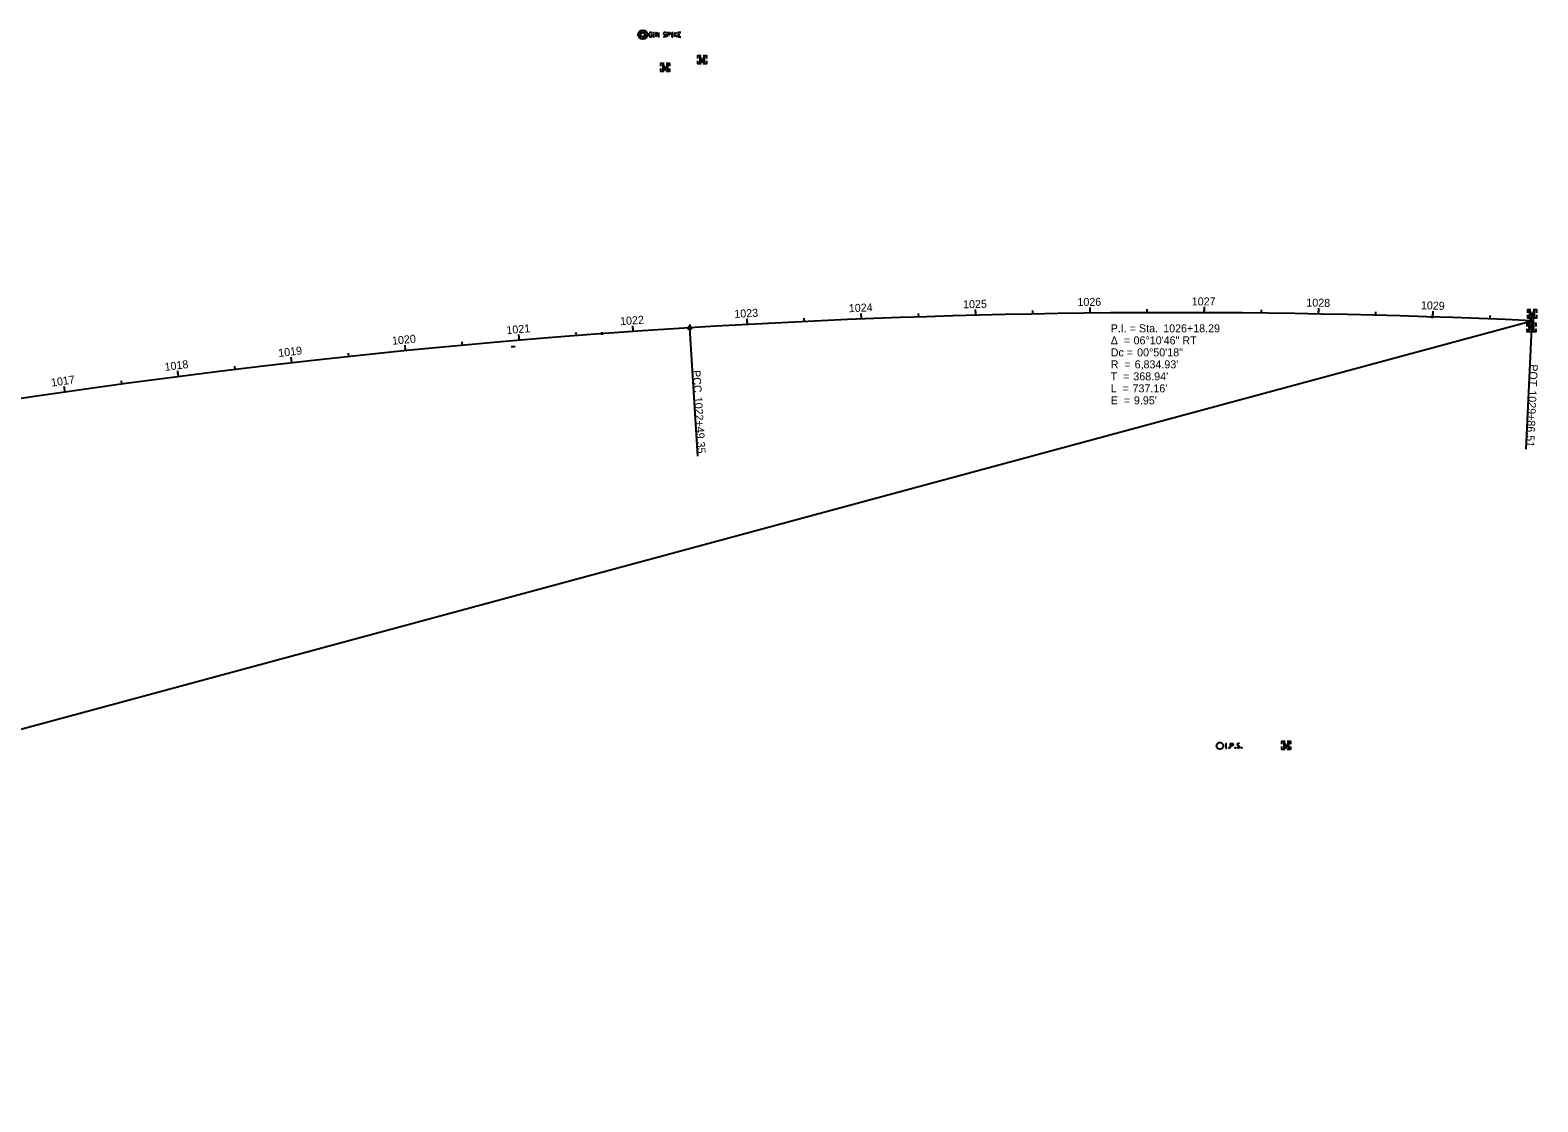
# Model space of a CAD drawing. Extents: x 2192033 to 2198234, y 657975 to 662607.
# Drawn here: x 2196682 to 2198001, y 661069 to 662007 of the extents above; entities that cross this region are included whole.
import ezdxf

# ---------------------------------------------------------------- set-up
doc = ezdxf.new("R2010")
doc.units = 0
for name, color, linetype in [('BR_P_Gen_Approach_Slab', 7, 'Continuous'), ('Default', 7, 'Continuous'), ('GE_X_Alignment_1000_Curve_Data', 7, 'Continuous'), ('GE_X_Alignment_1000_Stations', 7, 'Continuous'), ('GE_X_Alignment_100_Curve_Data', 7, 'Continuous'), ('GE_X_Alignment_100_Stations', 7, 'Continuous'), ('GE_X_Alignment_500_Curve_Data', 7, 'Continuous'), ('GE_X_Alignment_500_Stations', 7, 'Continuous'), ('PV_P_Joint', 7, 'Continuous'), ('RD_P_Text', 7, 'Continuous'), ('SH_Border', 7, 'Continuous'), ('SH_Data', 7, 'Continuous'), ('SH_Named_Boundary', 7, 'Continuous')]:
    doc.layers.add(name, color=color, linetype=linetype)

msp = doc.modelspace()

# ---------------------------------------------------------------- linework, layer by layer
at = {"layer": 'BR_P_Gen_Approach_Slab'}
for points in [[(2197728.4, 661382.9), (2197729.3, 661382.9)], [(2197728.4, 661378.9), (2197729.3, 661378.9)], [(2197728.8, 661378.9), (2197728.8, 661382.9)], [(2197731.2, 661379.4), (2197731.4, 661379.4), (2197731.4, 661379.4), (2197731.5, 661379.3), (2197731.5, 661379.1), (2197731.4, 661379), (2197731.4, 661378.9), (2197731.2, 661378.9), (2197731.1, 661379), (2197731.1, 661379.1), (2197731.1, 661379.3), (2197731.1, 661379.4), (2197731.2, 661379.4)], [(2197732.7, 661378.9), (2197732.7, 661382.9), (2197734.1, 661382.9), (2197734.2, 661382.9), (2197734.4, 661382.8), (2197734.5, 661382.8), (2197734.6, 661382.7), (2197734.7, 661382.5), (2197734.7, 661382.4), (2197734.8, 661382.1), (2197734.8, 661381.7), (2197734.8, 661381.6), (2197734.7, 661381.4), (2197734.6, 661381.2), (2197734.5, 661381.1), (2197734.4, 661381.1), (2197734.3, 661381), (2197734.1, 661381), (2197732.7, 661381)], [(2197736.8, 661379.4), (2197737, 661379.4), (2197737.1, 661379.4), (2197737.1, 661379.3), (2197737.1, 661379.1), (2197737.1, 661379), (2197737, 661378.9), (2197736.8, 661378.9), (2197736.8, 661379), (2197736.7, 661379.1), (2197736.7, 661379.3), (2197736.8, 661379.4), (2197736.8, 661379.4)], [(2197740.3, 661382.6), (2197740.2, 661382.7), (2197740.1, 661382.8), (2197739.9, 661382.9), (2197739.6, 661382.9), (2197739.4, 661382.9), (2197739.3, 661382.9), (2197738.9, 661382.8), (2197738.6, 661382.6), (2197738.4, 661382.4), (2197738.4, 661382.1), (2197738.4, 661381.9), (2197738.4, 661381.7), (2197738.6, 661381.5), (2197740.2, 661380.5), (2197740.3, 661380.4), (2197740.3, 661380.3), (2197740.4, 661380.1), (2197740.4, 661379.9), (2197740.4, 661379.7), (2197740.3, 661379.6), (2197740.3, 661379.4), (2197740.2, 661379.3), (2197740.2, 661379.2), (2197740.1, 661379.1), (2197740, 661379), (2197739.9, 661379), (2197739.8, 661378.9), (2197739.6, 661378.9), (2197739.2, 661378.9), (2197738.9, 661379), (2197738.6, 661379.2), (2197738.4, 661379.4)], [(2197742.3, 661379.4), (2197742.4, 661379.4), (2197742.5, 661379.4), (2197742.6, 661379.3), (2197742.6, 661379.1), (2197742.5, 661379), (2197742.4, 661378.9), (2197742.3, 661378.9), (2197742.2, 661379), (2197742.1, 661379.1), (2197742.1, 661379.3), (2197742.2, 661379.4), (2197742.3, 661379.4)]]:
    msp.add_lwpolyline(points, dxfattribs=at)
msp.add_circle((2197723.3, 661380.9), 3, dxfattribs=at)
at = {"layer": 'Default'}
msp.add_arc((2197684.2, 654882.2), 6872.3, 94.8201, 94.85002, dxfattribs=at)
at = {"layer": 'GE_X_Alignment_1000_Stations'}
for p, q in [((2197509.8, 661757.6), (2197509.7, 661760.6)), ((2197259.4, 661746.6), (2197266.4, 661634.3)), ((2197996.1, 661752.8), (2197991, 661640.5)), ((2197010.8, 661726.5), (2197010.4, 661731.5))]:
    msp.add_line(p, q, dxfattribs=at)
for centre in [(2197259.4, 661746.6), (2197996.1, 661752.8)]:
    msp.add_circle(centre, 1.5, dxfattribs=at)
at = {"layer": 'GE_X_Alignment_100_Stations'}
for p, q in [((2197409.8, 661754.3), (2197409.6, 661759.3)), ((2197459.8, 661756.2), (2197459.7, 661759.2)), ((2197509.8, 661757.6), (2197509.6, 661762.6)), ((2197559.8, 661758.7), (2197559.7, 661761.7)), ((2197609.7, 661759.5), (2197609.7, 661764.5)), ((2197659.7, 661759.9), (2197659.7, 661762.9)), ((2197709.7, 661759.9), (2197709.8, 661764.9)), ((2197759.7, 661759.5), (2197759.8, 661762.5)), ((2197809.7, 661758.8), (2197809.8, 661763.8)), ((2197859.7, 661757.7), (2197859.8, 661760.7)), ((2197909.7, 661756.2), (2197909.9, 661761.2)), ((2197210.1, 661743.4), (2197209.8, 661748.3)), ((2197259.4, 661746.6), (2197266.4, 661634.3)), ((2197260, 661746.6), (2197259.8, 661749.6)), ((2197309.9, 661749.6), (2197309.7, 661754.6)), ((2197359.9, 661752.1), (2197359.7, 661755.1)), ((2197959.7, 661754.4), (2197959.8, 661757.4)), ((2197996.1, 661752.8), (2197991, 661640.5)), ((2197060.6, 661731.3), (2197060.3, 661734.3)), ((2197110.4, 661735.7), (2197110, 661740.7)), ((2197160.3, 661739.7), (2197160, 661742.7)), ((2196911.4, 661716), (2196910.8, 661720.9)), ((2196961.1, 661721.4), (2196960.8, 661724.4)), ((2197010.8, 661726.5), (2197010.4, 661731.5)), ((2196812.1, 661704), (2196811.5, 661708.9)), ((2196861.7, 661710.1), (2196861.4, 661713.1)), ((2196713, 661690.5), (2196712.3, 661695.4)), ((2196762.6, 661697.4), (2196762.2, 661700.4))]:
    msp.add_line(p, q, dxfattribs=at)
for centre in [(2197259.4, 661746.6), (2197996.1, 661752.8)]:
    msp.add_circle(centre, 1.5, dxfattribs=at)
at = {"layer": 'GE_X_Alignment_500_Stations'}
for p, q in [((2197509.8, 661757.6), (2197509.6, 661762.6)), ((2197609.7, 661759.5), (2197609.7, 661762.5)), ((2197709.7, 661759.9), (2197709.8, 661762.9)), ((2197809.7, 661758.8), (2197809.8, 661761.8)), ((2197909.7, 661756.2), (2197909.8, 661759.2)), ((2197210.1, 661743.4), (2197209.9, 661746.3)), ((2197259.4, 661746.6), (2197266.4, 661634.3)), ((2197309.9, 661749.6), (2197309.8, 661752.6)), ((2197409.8, 661754.3), (2197409.7, 661757.3)), ((2197996.1, 661752.8), (2197991, 661640.5)), ((2197110.4, 661735.7), (2197110.2, 661738.7)), ((2197010.8, 661726.5), (2197010.4, 661731.5)), ((2196812.1, 661704), (2196811.7, 661706.9)), ((2196911.4, 661716), (2196911.1, 661719)), ((2196713, 661690.5), (2196712.6, 661693.5))]:
    msp.add_line(p, q, dxfattribs=at)
for centre in [(2197259.4, 661746.6), (2197996.1, 661752.8)]:
    msp.add_circle(centre, 1.5, dxfattribs=at)
at = {"layer": 'PV_P_Joint'}
for p, q in [((2197216.5, 662003.2), (2197214.4, 662003.2)), ((2197217.1, 662004.5), (2197215.6, 662006)), ((2197217.1, 662001.8), (2197215.6, 662000.3)), ((2197218.4, 662005), (2197218.4, 662007.2)), ((2197218.4, 662001.3), (2197218.4, 661999.2)), ((2197219.7, 662004.5), (2197221.3, 662006)), ((2197219.7, 662001.8), (2197221.3, 662000.3)), ((2197220.3, 662003.2), (2197222.4, 662003.2))]:
    msp.add_line(p, q, dxfattribs=at)
for points in [[(2197226.4, 662004.4), (2197226.4, 662004.5), (2197226.3, 662004.7), (2197226.1, 662004.8), (2197225.9, 662005), (2197225.7, 662005.1), (2197225.6, 662005.1), (2197225.4, 662005.2), (2197225, 662005.2), (2197224.9, 662005.1), (2197224.8, 662005.1), (2197224.7, 662005), (2197224.4, 662004.8), (2197224.2, 662004.6), (2197224.2, 662004.4), (2197224.1, 662004), (2197224, 662003.5), (2197224, 662002.9), (2197224.1, 662002.3), (2197224.2, 662001.9), (2197224.4, 662001.5), (2197224.5, 662001.4), (2197224.7, 662001.3), (2197225.1, 662001.2), (2197225.4, 662001.2), (2197225.8, 662001.2), (2197225.9, 662001.3), (2197226, 662001.3), (2197226.1, 662001.5), (2197226.3, 662001.7), (2197226.4, 662001.9), (2197226.4, 662002.7), (2197225.7, 662002.7)], [(2197227.7, 662005.2), (2197228.7, 662005.2)], [(2197227.7, 662001.2), (2197228.7, 662001.2)], [(2197228.2, 662001.2), (2197228.2, 662005.2)], [(2197230, 662001.2), (2197230, 662005.2), (2197232.3, 662001.2), (2197232.3, 662005.2)], [(2197238.6, 662004.9), (2197238.6, 662004.9), (2197238.5, 662005), (2197238.2, 662005.1), (2197237.9, 662005.2), (2197237.6, 662005.2), (2197237.5, 662005.2), (2197237.1, 662005.1), (2197236.8, 662004.9), (2197236.5, 662004.6), (2197236.5, 662004.4), (2197236.5, 662004.2), (2197236.5, 662003.9), (2197236.8, 662003.7), (2197238.5, 662002.8), (2197238.7, 662002.6), (2197238.7, 662002.5), (2197238.8, 662002.3), (2197238.8, 662002.1), (2197238.8, 662001.9), (2197238.7, 662001.8), (2197238.7, 662001.7), (2197238.6, 662001.5), (2197238.5, 662001.4), (2197238.5, 662001.3), (2197238.4, 662001.3), (2197238.2, 662001.2), (2197238.1, 662001.2), (2197237.9, 662001.2), (2197237.4, 662001.2), (2197237.1, 662001.2), (2197236.7, 662001.4), (2197236.5, 662001.6)], [(2197240, 662001.2), (2197240, 662005.2), (2197241.5, 662005.2), (2197241.7, 662005.1), (2197241.9, 662005.1), (2197242, 662005), (2197242.1, 662004.9), (2197242.2, 662004.8), (2197242.3, 662004.6), (2197242.4, 662004.4), (2197242.4, 662004), (2197242.3, 662003.9), (2197242.3, 662003.7), (2197242.1, 662003.5), (2197242, 662003.4), (2197241.9, 662003.3), (2197241.8, 662003.2), (2197241.5, 662003.2), (2197240, 662003.2)], [(2197243.7, 662005.2), (2197244.7, 662005.2)], [(2197243.7, 662001.2), (2197244.7, 662001.2)], [(2197244.2, 662001.2), (2197244.2, 662005.2)], [(2197246, 662005.2), (2197246, 662001.2)], [(2197247.8, 662005.2), (2197246, 662002.6)], [(2197246.6, 662003.4), (2197248.1, 662001.2)], [(2197251.6, 662005.2), (2197249.4, 662005.2), (2197249.4, 662001.2), (2197251.7, 662001.2)], [(2197249.4, 662003.2), (2197250.9, 662003.2)]]:
    msp.add_lwpolyline(points, dxfattribs=at)
for radius in [4, 1.88]:
    msp.add_circle((2197218.4, 662003.2), radius, dxfattribs=at)
at = {"layer": 'RD_P_Text'}
for centre, radius, start, end in [((2197685.6, 654925), 6834.9, 87.39548, 93.57492), ((2197687.9, 654887.7), 6872.3, 93.57492, 115.59076)]:
    msp.add_arc(centre, radius, start, end, dxfattribs=at)
at = {"layer": 'SH_Border'}
for p, q in [((2192833.4, 660357.6), (2197996.1, 661752.8)), ((2197995.9, 661746.8), (2197996.4, 661758.9))]:
    msp.add_line(p, q, dxfattribs=at)
at = {"layer": 'SH_Data'}
for p, q in [((2197907.6, 661756.2), (2197910.1, 661756.2)), ((2197908.9, 661757.5), (2197908.9, 661755)), ((2197908.9, 661756.2), (2197908.9, 661756.2)), ((2197181.2, 661741.6), (2197183.7, 661741.6)), ((2197182.5, 661742.9), (2197182.5, 661740.4)), ((2197182.5, 661741.6), (2197182.5, 661741.6))]:
    msp.add_line(p, q, dxfattribs=at)
at = {"layer": 'SH_Named_Boundary'}
for p, q in [((2197238.1, 661974.7), (2197238.1, 661974.7)), ((2197270.3, 661981.3), (2197270.3, 661981.3)), ((2197995.9, 661746.8), (2197995.9, 661746.8)), ((2197996.4, 661758.9), (2197996.4, 661758.9)), ((2197781.4, 661381.3), (2197781.4, 661381.3))]:
    msp.add_line(p, q, dxfattribs=at)
for points in [[(2197266.6, 661982.3), (2197266.6, 661985.1), (2197269.4, 661985.1)], [(2197268.5, 661978.8), (2197268.5, 661983.8), (2197270.3, 661978.8), (2197272.2, 661983.8), (2197272.2, 661978.8)], [(2197271.2, 661985.1), (2197274.1, 661985.1), (2197274.1, 661982.3)], [(2197234.3, 661975.6), (2197234.3, 661978.4), (2197237.1, 661978.4)], [(2197237.1, 661970.9), (2197234.3, 661970.9), (2197234.3, 661973.7)], [(2197236.2, 661972.2), (2197236.2, 661977.2), (2197238.1, 661972.2), (2197239.9, 661977.2), (2197239.9, 661972.2)], [(2197239, 661978.4), (2197241.8, 661978.4), (2197241.8, 661975.6)], [(2197241.8, 661973.7), (2197241.8, 661970.9), (2197239, 661970.9)], [(2197269.4, 661977.6), (2197266.6, 661977.6), (2197266.6, 661980.4)], [(2197274.1, 661980.4), (2197274.1, 661977.6), (2197271.2, 661977.6)], [(2197992.7, 661759.8), (2197992.7, 661762.6), (2197995.5, 661762.6)], [(2197994.6, 661756.4), (2197994.6, 661761.4), (2197996.4, 661756.4), (2197998.3, 661761.4), (2197998.3, 661756.4)], [(2197997.3, 661762.6), (2198000.2, 661762.6), (2198000.2, 661759.8)], [(2197992.1, 661747.8), (2197992.1, 661750.6), (2197994.9, 661750.6)], [(2197995.5, 661755.1), (2197992.7, 661755.1), (2197992.7, 661757.9)], [(2197994, 661744.3), (2197994, 661749.3), (2197995.9, 661744.3), (2197997.7, 661749.3), (2197997.7, 661744.3)], [(2197996.8, 661750.6), (2197999.6, 661750.6), (2197999.6, 661747.8)], [(2198000.2, 661757.9), (2198000.2, 661755.1), (2197997.3, 661755.1)], [(2197994.9, 661743.1), (2197992.1, 661743.1), (2197992.1, 661745.9)], [(2197999.6, 661745.9), (2197999.6, 661743.1), (2197996.8, 661743.1)], [(2197777.6, 661382.3), (2197777.6, 661385.1), (2197780.4, 661385.1)], [(2197780.4, 661377.6), (2197777.6, 661377.6), (2197777.6, 661380.4)], [(2197779.5, 661378.8), (2197779.5, 661383.8), (2197781.4, 661378.8), (2197783.2, 661383.8), (2197783.2, 661378.8)], [(2197782.3, 661385.1), (2197785.1, 661385.1), (2197785.1, 661382.3)], [(2197785.1, 661380.4), (2197785.1, 661377.6), (2197782.3, 661377.6)]]:
    msp.add_lwpolyline(points, dxfattribs=at)

# ---------------------------------------------------------------- texts
at = {"layer": 'GE_X_Alignment_1000_Curve_Data'}
for s, p in [('P.I. = Sta. ', (2197627.8, 661742.7)), ('1026+18.29', (2197673.7, 661742.7)), ('Δ  = ', (2197627.8, 661732.2)), ('06°10\'46" RT', (2197647.8, 661732.2)), ('Dc = ', (2197627.8, 661721.7)), ('00°50\'18"', (2197650.9, 661721.7)), ('T  = ', (2197627.8, 661700.7)), ('R  = ', (2197627.8, 661711.2)), ("368.94'", (2197647.6, 661700.7)), ("6,834.93'", (2197648.7, 661711.2)), ('L  = ', (2197627.8, 661690.2)), ("737.16'", (2197646.9, 661690.2)), ('E  = ', (2197627.8, 661679.7)), ("9.95'", (2197648.1, 661679.7))]:
    msp.add_text(s, height=7, dxfattribs=at).set_placement(p)
at = {"layer": 'GE_X_Alignment_1000_Stations'}
for s, rotation, p in [('1020', 5.6538, (2196999.4, 661731.8)), ('PCC', 273.5749, (2197261.8, 661709.4)), ('POT', 267.3955, (2197994.5, 661714.9)), ('1022+49.35', 273.5749, (2197263.3, 661686.1)), ('1029+86.51', 267.3955, (2197993.5, 661692.1))]:
    msp.add_text(s, height=7, rotation=rotation, dxfattribs=at).set_placement(p)
at = {"layer": 'GE_X_Alignment_100_Curve_Data'}
for s, p in [('P.I. = Sta. ', (2197627.8, 661742.7)), ('1026+18.29', (2197673.7, 661742.7)), ('Δ  = ', (2197627.8, 661732.2)), ('06°10\'46" RT', (2197647.8, 661732.2)), ('Dc = ', (2197627.8, 661721.7)), ('00°50\'18"', (2197650.9, 661721.7)), ('T  = ', (2197627.8, 661700.7)), ('R  = ', (2197627.8, 661711.2)), ("368.94'", (2197647.6, 661700.7)), ("6,834.93'", (2197648.7, 661711.2)), ('L  = ', (2197627.8, 661690.2)), ("737.16'", (2197646.9, 661690.2)), ('E  = ', (2197627.8, 661679.7)), ("9.95'", (2197648.1, 661679.7))]:
    msp.add_text(s, height=7, dxfattribs=at).set_placement(p)
at = {"layer": 'GE_X_Alignment_100_Stations'}
for s, rotation, p in [('1026', 0.6355, (2197598.7, 661765.7)), ('1027', 359.7972, (2197698.7, 661766.3)), ('1028', 358.959, (2197798.9, 661765.3)), ('1023', 3.1504, (2197298.7, 661755.3)), ('1024', 2.3121, (2197398.8, 661760.3)), ('1025', 1.4738, (2197498.7, 661763.7)), ('1029', 358.1207, (2197899.1, 661763)), ('1021', 4.8201, (2197099.4, 661741.1)), ('1022', 3.9864, (2197198.8, 661748.9)), ('1020', 5.6538, (2196999.4, 661731.8)), ('1019', 6.4875, (2196899.9, 661721.1)), ('1018', 7.3213, (2196800.5, 661708.9)), ('PCC', 273.5749, (2197261.8, 661709.4)), ('POT', 267.3955, (2197994.5, 661714.9)), ('1017', 8.155, (2196701.2, 661695.2)), ('1022+49.35', 273.5749, (2197263.3, 661686.1)), ('1029+86.51', 267.3955, (2197993.5, 661692.1))]:
    msp.add_text(s, height=7, rotation=rotation, dxfattribs=at).set_placement(p)
at = {"layer": 'GE_X_Alignment_500_Curve_Data'}
for s, p in [('P.I. = Sta. ', (2197627.8, 661742.7)), ('1026+18.29', (2197673.7, 661742.7)), ('Δ  = ', (2197627.8, 661732.2)), ('06°10\'46" RT', (2197647.8, 661732.2)), ('Dc = ', (2197627.8, 661721.7)), ('00°50\'18"', (2197650.9, 661721.7)), ('T  = ', (2197627.8, 661700.7)), ('R  = ', (2197627.8, 661711.2)), ("368.94'", (2197647.6, 661700.7)), ("6,834.93'", (2197648.7, 661711.2)), ('L  = ', (2197627.8, 661690.2)), ("737.16'", (2197646.9, 661690.2)), ('E  = ', (2197627.8, 661679.7)), ("9.95'", (2197648.1, 661679.7))]:
    msp.add_text(s, height=7, dxfattribs=at).set_placement(p)
at = {"layer": 'GE_X_Alignment_500_Stations'}
for s, rotation, p in [('1025', 1.4738, (2197498.7, 661763.7)), ('1020', 5.6538, (2196999.4, 661731.8)), ('PCC', 273.5749, (2197261.8, 661709.4)), ('POT', 267.3955, (2197994.5, 661714.9)), ('1022+49.35', 273.5749, (2197263.3, 661686.1)), ('1029+86.51', 267.3955, (2197993.5, 661692.1))]:
    msp.add_text(s, height=7, rotation=rotation, dxfattribs=at).set_placement(p)

doc.saveas('drawing.dxf')
